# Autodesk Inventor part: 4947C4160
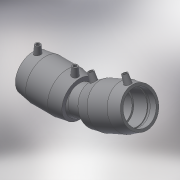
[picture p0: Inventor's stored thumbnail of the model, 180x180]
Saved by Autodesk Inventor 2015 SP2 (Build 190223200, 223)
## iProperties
Created: 2017-06
Part Number: 4947C4160
Material: Generic
Description: PLASSON ADJUSTABLE ELBOW 160
Document SubType Name: Modeling
Designer: KIM
Mass: 55.0731 g
Surface Area: 148.067 cm^2
Volume: 55.0731 cm^3
Density: 1 g/cm^3
Appearance: Default
Author: KIM
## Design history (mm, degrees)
derived "4947C4.ipt"
feature "Solid1::4947C4.ipt"
tag "TaggingFeature1"
body "Solid1"
other parameters: "d0" = 182.4, "d3" = 92, "d4" = 46, "d8" = 168 deg, "d10" = 36.8, "d11" = 12.26667, "d29" = 114, "d30" = 15, "d31" = 72.96, "d34" = 5 deg, "d41" = 4, "d42" = 14, "d43" = 0, "d48" = 144, "d49" = 24 deg, "d50" = 456, "d51" = 78 deg, "d52" = 90 deg, "d55" = 45.2, "d57" = 168 deg, "d58" = 9.04, "d60" = 54.03344, "d62" = 3, "d63" = 0, "L_" = 456, "L_1" = 92, "A_" = 114, "d_2" = 12, "L_0" = 148, "d54" = 90.4, "d59" = 180.11148
